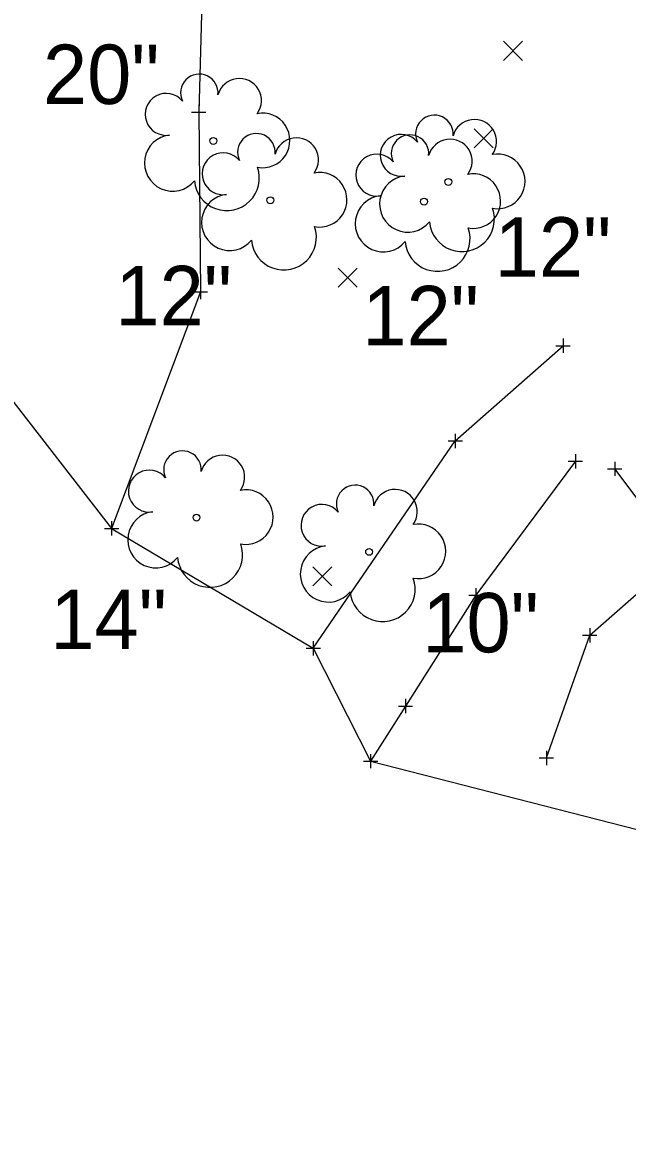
# Model space of a CAD drawing. Extents: x 2005176 to 2005823, y 572472 to 572942.
# Drawn here: x 2005452.2 to 2005494.7, y 572472.3 to 572551.1 of the extents above; entities that cross this region are included whole.
import ezdxf

# ---------------------------------------------------------------- set-up
doc = ezdxf.new("R2010")
doc.units = 0
for name, color, linetype in [('GE_X_Alignment_500_Bearings', 7, 'Continuous'), ('SV_P_Mon_Cells_Set', 7, 'Continuous'), ('SV_X_Random_Point', 7, 'Continuous'), ('SV_X_Shot_Marker', 7, 'Continuous'), ('SV_X_Terrain_Boundary', 7, 'Continuous'), ('VG_X_Text', 7, 'Continuous')]:
    doc.layers.add(name, color=color, linetype=linetype)

msp = doc.modelspace()

# ---------------------------------------------------------------- linework, layer by layer
at = {"layer": 'GE_X_Alignment_500_Bearings'}
for points in [[(2005471.535, 572579.333), (2005465.091, 572562.814), (2005464.598, 572544.768), (2005464.708, 572532.148), (2005458.479, 572515.558)], [(2005472.631, 572507.15), (2005482.596, 572521.698), (2005490.158, 572528.372)], [(2005491.028, 572520.264), (2005484.048, 572510.865), (2005479.103, 572503.097), (2005476.652, 572499.232)], [(2005488.988, 572499.456), (2005492.028, 572508.058), (2005498.368, 572513.628), (2005493.781, 572519.739)]]:
    msp.add_lwpolyline(points, dxfattribs=at)
at = {"layer": 'SV_P_Mon_Cells_Set'}
for p, q in [((2005464.598, 572545.268), (2005464.598, 572544.268)), ((2005464.098, 572544.768), (2005465.098, 572544.768)), ((2005464.598, 572544.768), (2005464.598, 572544.768)), ((2005464.708, 572532.648), (2005464.708, 572531.648)), ((2005464.208, 572532.148), (2005465.208, 572532.148)), ((2005464.708, 572532.148), (2005464.708, 572532.148)), ((2005490.158, 572528.872), (2005490.158, 572527.872)), ((2005489.658, 572528.372), (2005490.658, 572528.372)), ((2005490.158, 572528.372), (2005490.158, 572528.372)), ((2005482.596, 572522.198), (2005482.596, 572521.198)), ((2005482.096, 572521.698), (2005483.096, 572521.698)), ((2005482.596, 572521.698), (2005482.596, 572521.698)), ((2005491.028, 572520.764), (2005491.028, 572519.764)), ((2005490.528, 572520.264), (2005491.528, 572520.264)), ((2005491.028, 572520.264), (2005491.028, 572520.264)), ((2005493.781, 572520.239), (2005493.781, 572519.239)), ((2005493.281, 572519.739), (2005494.281, 572519.739)), ((2005493.781, 572519.739), (2005493.781, 572519.739)), ((2005458.479, 572516.058), (2005458.479, 572515.058)), ((2005457.979, 572515.558), (2005458.979, 572515.558)), ((2005458.479, 572515.558), (2005458.479, 572515.558)), ((2005484.048, 572511.365), (2005484.048, 572510.365)), ((2005483.548, 572510.865), (2005484.548, 572510.865)), ((2005484.048, 572510.865), (2005484.048, 572510.865)), ((2005491.528, 572508.058), (2005492.528, 572508.058)), ((2005492.028, 572508.558), (2005492.028, 572507.558)), ((2005492.028, 572508.058), (2005492.028, 572508.058)), ((2005472.631, 572507.65), (2005472.631, 572506.65)), ((2005472.131, 572507.15), (2005473.131, 572507.15)), ((2005472.631, 572507.15), (2005472.631, 572507.15)), ((2005479.103, 572503.597), (2005479.103, 572502.597)), ((2005478.603, 572503.097), (2005479.603, 572503.097)), ((2005479.103, 572503.097), (2005479.103, 572503.097)), ((2005476.652, 572499.732), (2005476.652, 572498.732)), ((2005488.488, 572499.456), (2005489.488, 572499.456)), ((2005488.988, 572499.956), (2005488.988, 572498.956)), ((2005488.988, 572499.456), (2005488.988, 572499.456)), ((2005476.152, 572499.232), (2005477.152, 572499.232)), ((2005476.652, 572499.232), (2005476.652, 572499.232))]:
    msp.add_line(p, q, dxfattribs=at)
at = {"layer": 'SV_X_Random_Point'}
for p, q in [((2005485.974, 572548.393), (2005487.307, 572549.728)), ((2005485.974, 572549.728), (2005487.307, 572548.393)), ((2005483.925, 572542.264), (2005485.258, 572543.6)), ((2005483.925, 572543.6), (2005485.258, 572542.264)), ((2005474.388, 572532.487), (2005475.721, 572533.823)), ((2005474.388, 572533.823), (2005475.721, 572532.487)), ((2005472.611, 572511.528), (2005473.944, 572512.863)), ((2005472.611, 572512.863), (2005473.944, 572511.528))]:
    msp.add_line(p, q, dxfattribs=at)
at = {"layer": 'SV_X_Shot_Marker'}
for centre in [(2005465.618, 572542.74), (2005482.114, 572539.865), (2005469.621, 572538.576), (2005480.403, 572538.481), (2005464.439, 572516.313), (2005476.551, 572513.912)]:
    msp.add_circle(centre, 0.24, dxfattribs=at)
for centre, radius, start, end in [((2005464.634, 572546.107), 1.317, 354.0047, 205.97412), ((2005467.444, 572545.569), 1.553, 323.82996, 165.0376), ((2005462.308, 572544.604), 1.471, 39.06254, 279.54124), ((2005469.078, 572542.775), 1.915, 259.14531, 101.45961), ((2005481.13, 572543.232), 1.317, 354.0047, 205.97412), ((2005483.94, 572542.694), 1.553, 323.82996, 165.0376), ((2005462.764, 572541.191), 1.974, 96.17219, 320.57371), ((2005468.637, 572541.944), 1.317, 354.0047, 205.97412), ((2005471.447, 572541.405), 1.553, 323.82996, 165.0376), ((2005478.805, 572541.729), 1.471, 39.06254, 279.54124), ((2005479.419, 572541.848), 1.317, 354.0047, 205.97412), ((2005482.229, 572541.31), 1.553, 323.82996, 165.0376), ((2005466.311, 572540.44), 1.471, 39.06254, 279.54124), ((2005477.093, 572540.345), 1.471, 39.06254, 279.54124), ((2005485.574, 572539.901), 1.915, 259.14531, 101.45961), ((2005466.564, 572540.134), 2.284, 184.94757, 19.45715), ((2005473.081, 572538.612), 1.915, 259.14531, 101.45961), ((2005483.863, 572538.517), 1.915, 259.14531, 101.45961), ((2005479.261, 572538.316), 1.974, 96.17219, 320.57371), ((2005466.767, 572537.028), 1.974, 96.17219, 320.57371), ((2005477.549, 572536.932), 1.974, 96.17219, 320.57371), ((2005483.06, 572537.259), 2.284, 184.94757, 19.45715), ((2005470.567, 572535.971), 2.284, 184.94757, 19.45715), ((2005481.349, 572535.875), 2.284, 184.94757, 19.45715), ((2005463.456, 572519.681), 1.317, 354.0047, 205.97412), ((2005466.266, 572519.142), 1.553, 323.82996, 165.0376), ((2005461.13, 572518.177), 1.471, 39.06254, 279.54124), ((2005467.9, 572516.349), 1.915, 259.14531, 101.45961), ((2005475.568, 572517.279), 1.317, 354.0047, 205.97412), ((2005478.377, 572516.741), 1.553, 323.82996, 165.0376), ((2005461.586, 572514.764), 1.974, 96.17219, 320.57371), ((2005473.242, 572515.776), 1.471, 39.06254, 279.54124), ((2005480.012, 572513.948), 1.915, 259.14531, 101.45961), ((2005465.386, 572513.708), 2.284, 184.94757, 19.45715), ((2005473.698, 572512.363), 1.974, 96.17219, 320.57371), ((2005477.498, 572511.307), 2.284, 184.94757, 19.45715)]:
    msp.add_arc(centre, radius, start, end, dxfattribs=at)
at = {"layer": 'SV_X_Terrain_Boundary'}
msp.add_lwpolyline([(2005414.704, 572571.993), (2005458.479, 572515.558), (2005472.631, 572507.15), (2005476.652, 572499.232), (2005498.182, 572493.714), (2005500.59, 572492.24), (2005514.667, 572482.565), (2005521.368, 572479.609), (2005532.268, 572476.648), (2005543.244, 572472.335), (2005552.271, 572478.109), (2005563.459, 572480.297), (2005570.757, 572499.94), (2005575.287, 572509.4), (2005587.95, 572518.639), (2005591.142, 572529.855), (2005622.825, 572562.218), (2005632.872, 572562.762), (2005676.665, 572561.819)], dxfattribs=at)

# ---------------------------------------------------------------- texts
at = {"layer": 'VG_X_Text'}
for s, p in [('20"', (2005453.667, 572545.33)), ('12"', (2005485.367, 572533.221)), ('12"', (2005458.75, 572529.809)), ('12"', (2005476.08, 572528.405)), ('14"', (2005454.186, 572507.097)), ('10"', (2005480.284, 572506.863))]:
    msp.add_text(s, height=4.1667, dxfattribs=at).set_placement(p)

doc.saveas('drawing.dxf')
